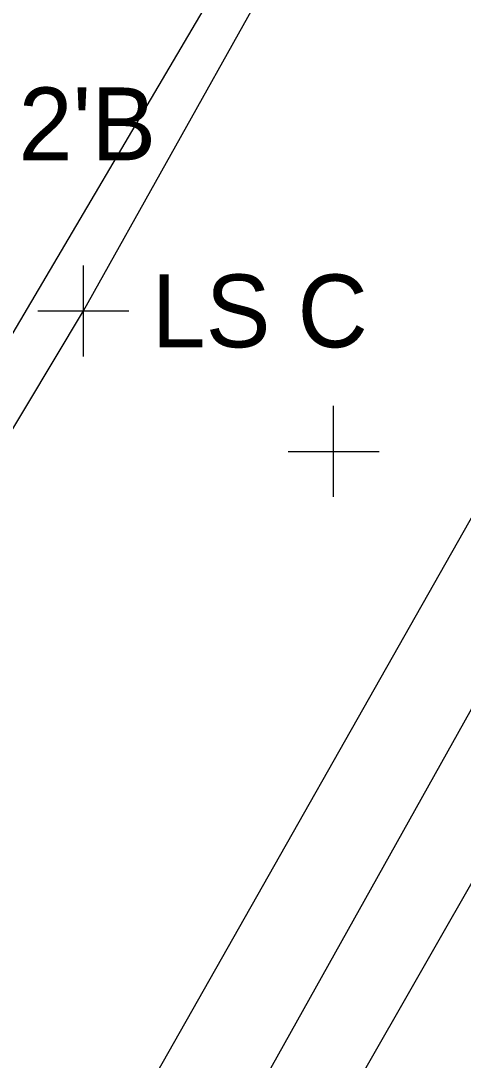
# Model space of a CAD drawing. Extents: x 1363693 to 1365209, y 422201 to 424153.
# Drawn here: x 1364102.71 to 1364112.45, y 422813.03 to 422835.87 of the extents above; entities that cross this region are included whole.
import ezdxf

# ---------------------------------------------------------------- set-up
doc = ezdxf.new("R2010")
doc.units = 0
for name, color, linetype in [('OWNERS', 7, 'Continuous'), ('PM_X_Channelizing_Line', 7, 'Continuous'), ('PM_X_Edge_Line', 7, 'Continuous'), ('SV_X_Original_Ground', 7, 'Continuous'), ('SV_X_Random_Point', 7, 'Continuous'), ('UT_X_FO', 7, 'Continuous'), ('UT_X_Gas', 7, 'Continuous'), ('VG_X_Flower_Bed', 7, 'Continuous'), ('VG_X_Text', 7, 'Continuous')]:
    doc.layers.add(name, color=color, linetype=linetype)

msp = doc.modelspace()

# ---------------------------------------------------------------- linework, layer by layer
at = {"layer": 'OWNERS'}
msp.add_lwpolyline([(1364089.632, 422780.271), (1364102.08, 422801.911), (1364114.271, 422823.678), (1364126.868, 422845.272), (1364138.192, 422867.568), (1364150.546, 422889.234), (1364150.546, 422889.234), (1364162.879, 422910.978), (1364162.879, 422910.978), (1364170.332, 422924.545), (1364170.332, 422924.545), (1364173.925, 422931.803), (1364173.925, 422931.803), (1364182.923, 422951.414), (1364182.923, 422951.414), (1364183.888, 422953.606), (1364183.888, 422953.606), (1364188.472, 422964.837), (1364188.472, 422964.837), (1364192.543, 422975.639), (1364192.543, 422975.639), (1364193.28, 422977.776), (1364193.28, 422977.776), (1364200.007, 422998.363)], dxfattribs=at)
at = {"layer": 'PM_X_Channelizing_Line'}
msp.add_line((1364103.568, 422801.079), (1364115.929, 422822.695), dxfattribs=at)
at = {"layer": 'PM_X_Edge_Line'}
msp.add_line((1364103.568, 422801.079), (1364115.929, 422822.695), dxfattribs=at)
at = {"layer": 'SV_X_Original_Ground'}
for p, q in [((1364109.592, 422825.405), (1364109.592, 422827.405)), ((1364108.592, 422826.405), (1364110.592, 422826.405))]:
    msp.add_line(p, q, dxfattribs=at)
at = {"layer": 'SV_X_Random_Point'}
for p, q in [((1364104.088, 422828.493), (1364104.088, 422830.493)), ((1364103.088, 422829.493), (1364105.088, 422829.493))]:
    msp.add_line(p, q, dxfattribs=at)
at = {"layer": 'UT_X_FO'}
msp.add_lwpolyline([(1364198.41, 423083.145), (1364202.916, 423079.215), (1364206.614, 423072.625), (1364206.927, 423065.384), (1364205.607, 423052.889), (1364202.652, 423033.176), (1364193.585, 423006.537), (1364182.955, 422981.103), (1364130.325, 422876.058), (1364040.63, 422724.214)], dxfattribs=at)
at = {"layer": 'UT_X_Gas'}
msp.add_lwpolyline([(1364207.557, 423089.372), (1364211.518, 423072.856), (1364208.943, 423046.381), (1364201.649, 423012.485), (1364191.712, 422981.617), (1364181.14, 422953.292), (1364166.466, 422921.961), (1364127.708, 422851.525), (1364051.86, 422717.903)], dxfattribs=at)
at = {"layer": 'VG_X_Flower_Bed'}
for p, q in [((1364104.088, 422829.493), (1364116.235, 422851.18)), ((1364091.259, 422808.103), (1364104.088, 422829.493))]:
    msp.add_line(p, q, dxfattribs=at)

# ---------------------------------------------------------------- texts
at = {"layer": 'SV_X_Random_Point'}
msp.add_text('LS C', height=1.6, dxfattribs=at).set_placement((1364105.588, 422828.693))
at = {"layer": 'VG_X_Text'}
msp.add_text("2'B", height=1.6, dxfattribs=at).set_placement((1364102.663, 422832.802))

doc.saveas('drawing.dxf')
